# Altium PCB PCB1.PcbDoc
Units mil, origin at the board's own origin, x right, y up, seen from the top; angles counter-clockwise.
Board outline 4950 x 3450 mil, 2 copper layers (Top Layer, Bottom Layer), stack 62 mil thick; 23 components, 0 nets, 12 pads, 0 vias.
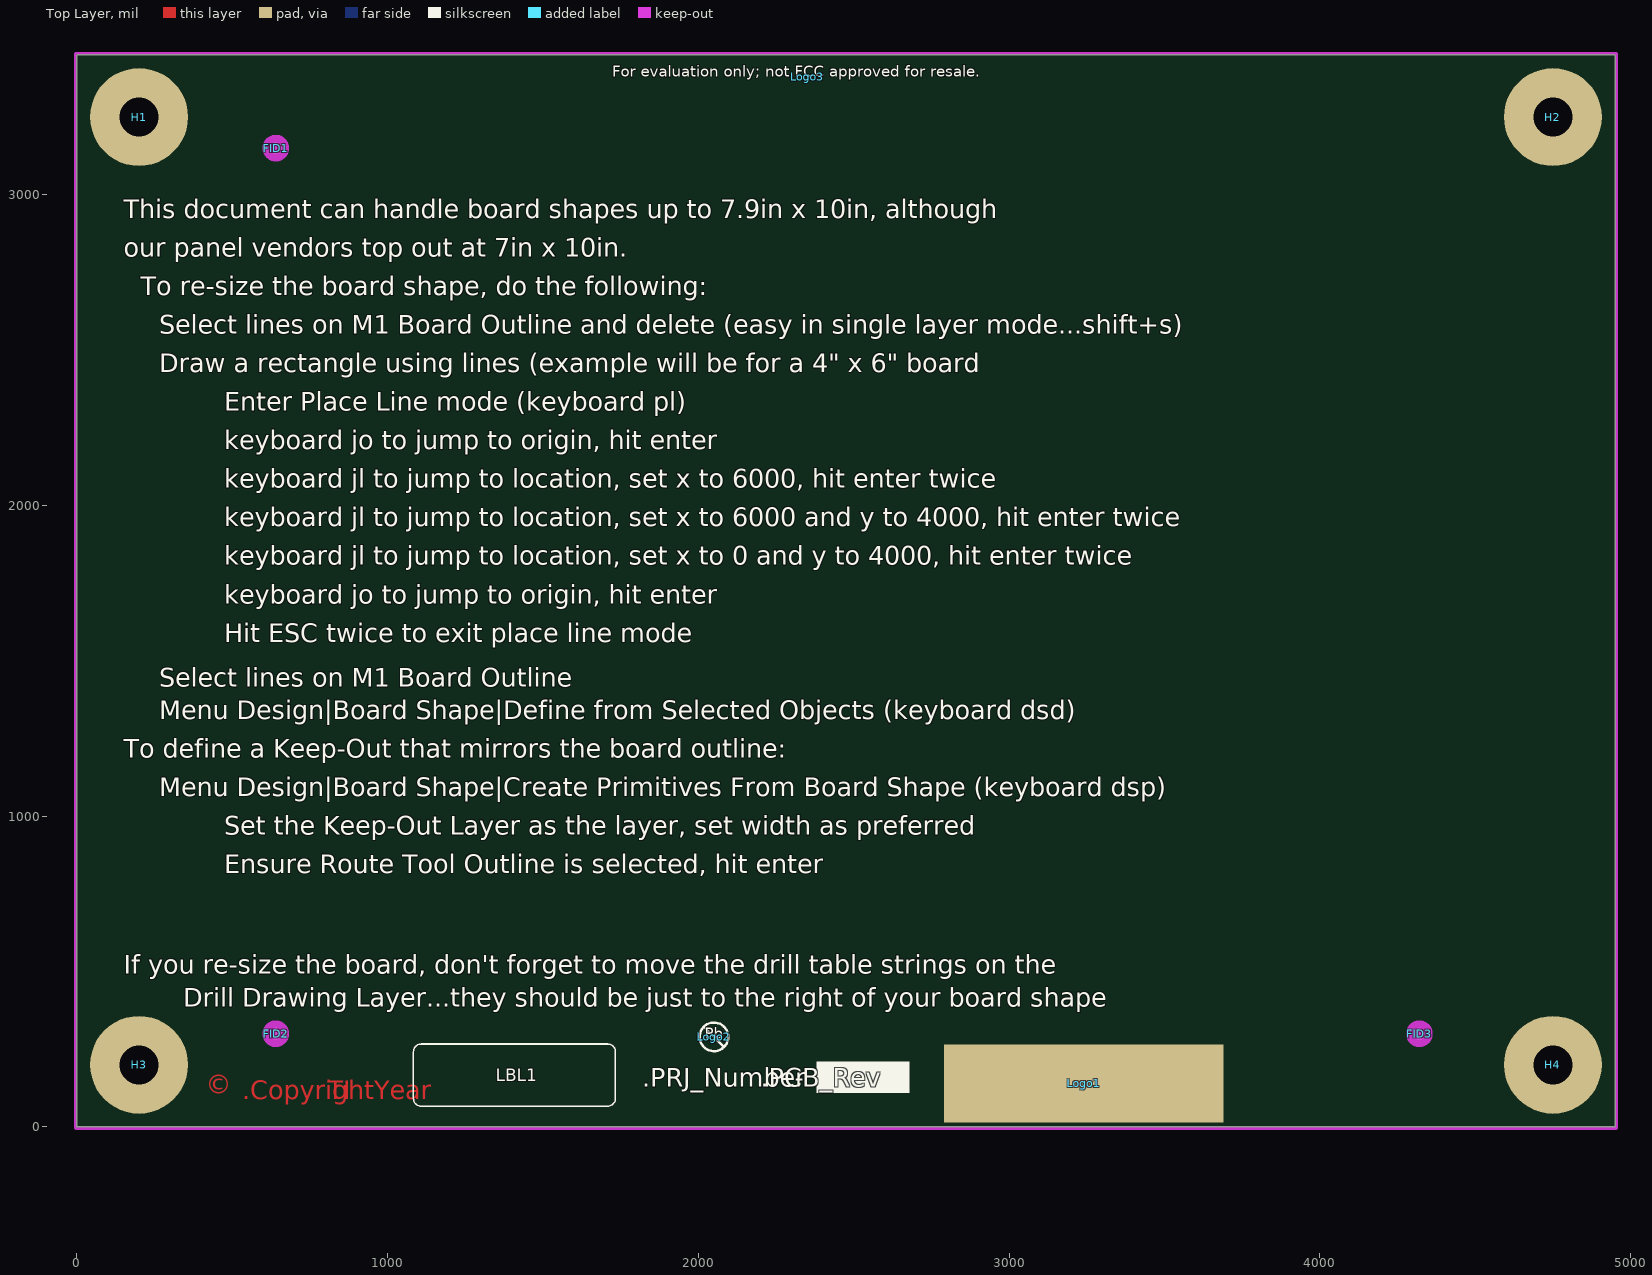
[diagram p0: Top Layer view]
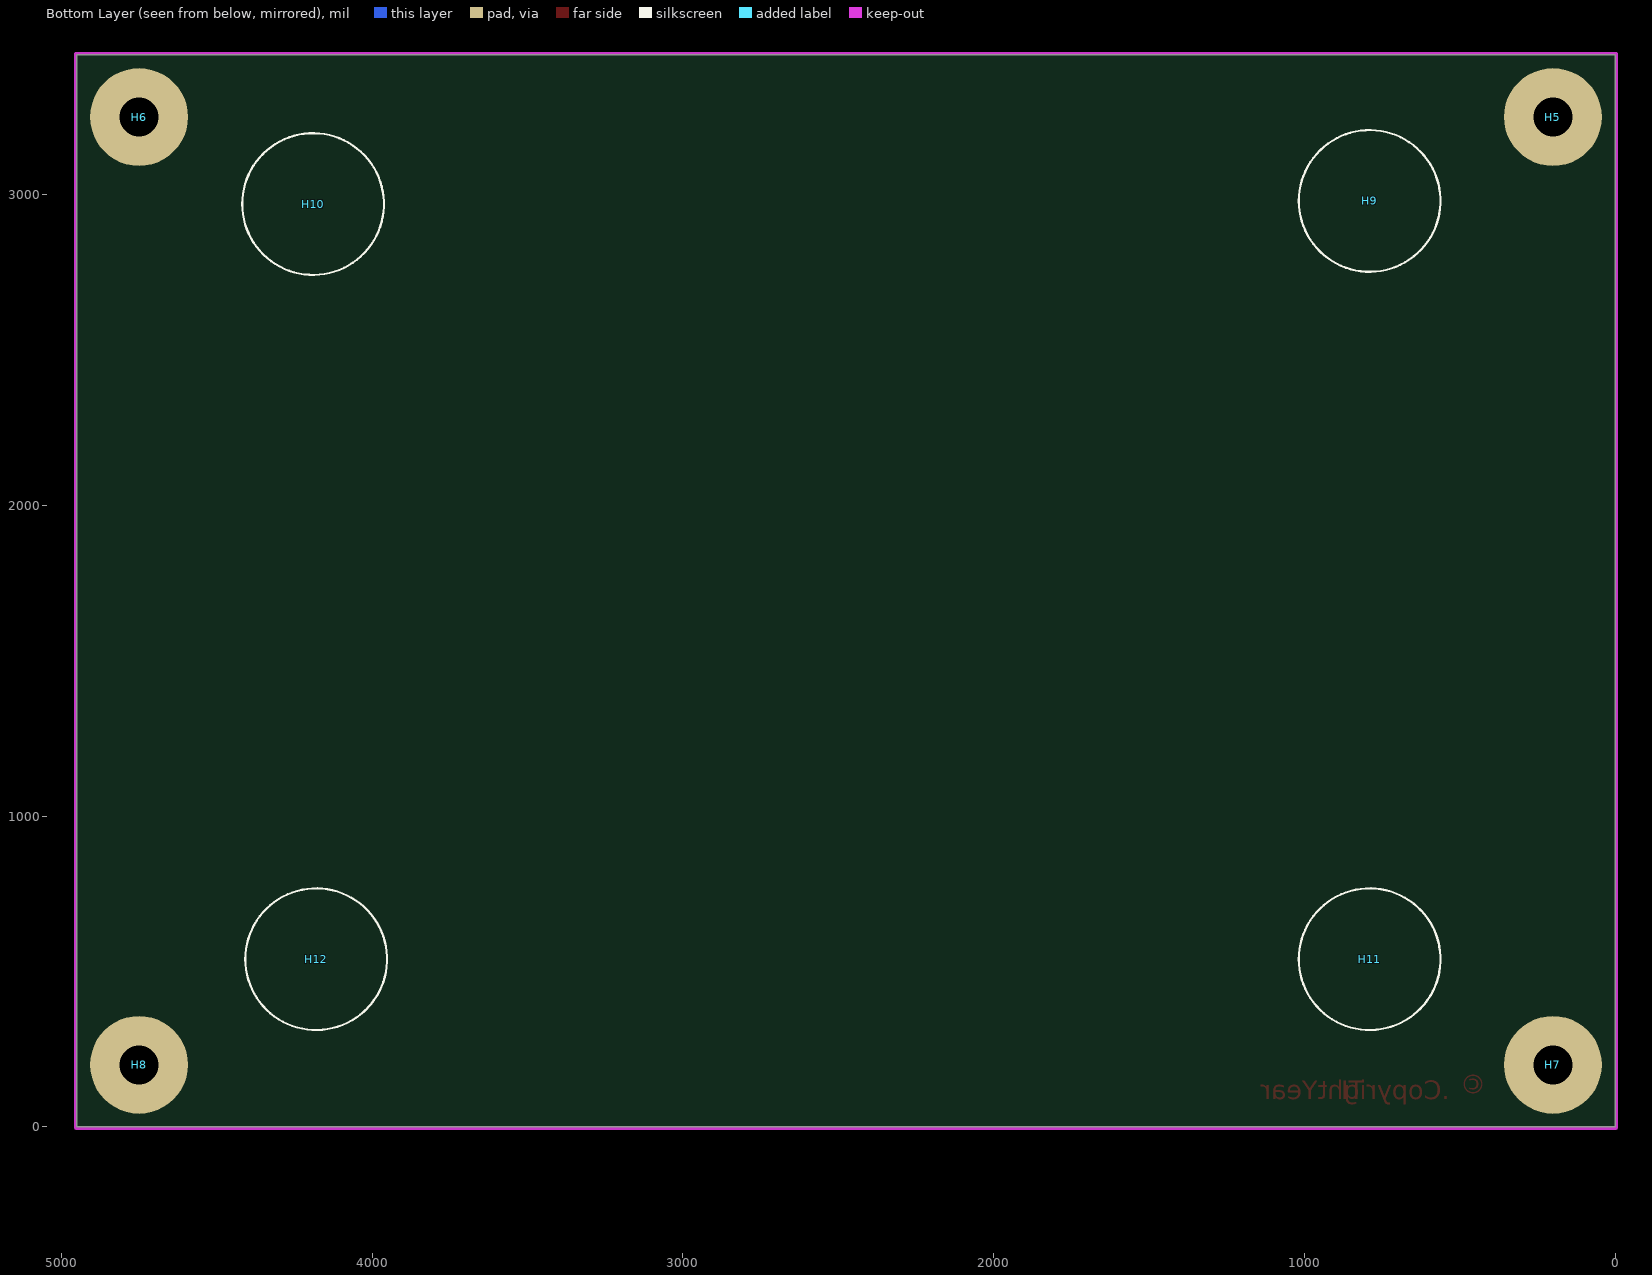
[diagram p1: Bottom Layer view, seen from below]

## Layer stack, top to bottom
Top Solder: solder mask 0.4, Solder Resist, Dk 3.5
Top Layer: signal copper 1.4
Dielectric1: core 59.2, FR-4, Dk 4.8
Bottom Layer: signal copper 1.4
Bottom Solder: solder mask 0.4, Solder Resist, Dk 3.5

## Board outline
0,0 4950,0 4950,3450 0,3450

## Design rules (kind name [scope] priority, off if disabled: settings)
AcuteAngle [All] p1: minimum=4.50000000000000E+0001 checktracksonly=FALSE
AssemblyTestPointUsage [All] p1: valid=2
Clearance Clearance_Keepouts [((IsTrack Or IsArc) And Not InPoly) And IsFree and IsKeepOut vs ((IsTrack Or IsArc) And Not InPoly) And IsFree and IsKeepOut] p1: gap=0
Clearance Clearance_BoardEdge_MountingHoles [OnCopper and InComponentClass('Mounting Holes') vs IsKeepOut] p2: gap=40
Clearance Clearance_BoardEdge_Poly [OnCopper and InPoly vs IsKeepOut] p3: gap=25
Clearance Clearance_BoardEdge [OnCopper and Not InComponentClass('Logo') and not InComponentClass('FiducialMark') and not InRegion(1000,500,4000,800) and Not IsKeepout vs IsKeepOut] p4: gap=75
Clearance Clearance_Poly [InPolygon] p5: gap=25
Clearance [All] p6: gap=7.87
ComponentClearance ComponentClearance_MountingHoles_FiducialMarks [InComponentClass('Mounting Holes') vs InComponentClass('FiducialMark')] p1: gap=50 collisioncheckmode=3 verticalgap=10 showdistances=FALSE
ComponentClearance ComponentClearance_Shunt [InComponentClass('Header') vs InComponentClass('Shunt')] p2: gap=0 collisioncheckmode=3 verticalgap=0 showdistances=FALSE
ComponentClearance ComponentClearance_Logo [InComponentClass('Logo')] p3: gap=50 collisioncheckmode=3 verticalgap=10 showdistances=FALSE
ComponentClearance ComponentClearance_ScrewToNut [(HasFootprint('NY PMS 440 0025 PH')) vs (HasFootprint('Keystone_1902C'))] p4: gap=5 collisioncheckmode=3 verticalgap=10 showdistances=FALSE
ComponentClearance ComponentClearance_MountingHoles [InComponentClass('Mounting Holes')] p5: gap=250 collisioncheckmode=3 verticalgap=100000 showdistances=FALSE
ComponentClearance ComponentClearance_SmallPassives [HasFootprint('0201*') or HasFootprint('0402*') or HasFootprint('0508') or HasFootprint('0603*') or HasFootprint('0612') or HasFootprint('0805*') or HasFootprint('0815*') or HasFootprint('0830*') or HasFootprint('1206*') or HasFootprint('1210*') or HasFootprint('1808*') or HasFootprint('1812*') or HasFootprint('1825*') or HasFootprint('2010*') or HasFootprint('2220*') or HasFootprint('2225*') or HasFootprint('2512*') or HasFootprint('2728*') or HasFootprint('3518*') vs HasFootprint('0201*') or HasFootprint('0402*') or HasFootprint('0508') or HasFootprint('0603*') or HasFootprint('0612') or HasFootprint('0805*') or HasFootprint('0815*') or HasFootprint('0830*') or HasFootprint('1206*') or HasFootprint('1210*') or HasFootprint('1808*') or HasFootprint('1812*') or HasFootprint('1825*') or HasFootprint('2010*') or HasFootprint('2220*') or HasFootprint('2225*') or HasFootprint('2512*') or HasFootprint('2728*') or HasFootprint('3518*')] p6: gap=20 collisioncheckmode=3 verticalgap=10 showdistances=FALSE
ComponentClearance ComponentClearance_THtoSMT [IsThruComponent vs IsSMTComponent] p7: gap=100 collisioncheckmode=3 verticalgap=30 showdistances=FALSE
ComponentClearance ComponentClearance_THtoTH [IsThruComponent vs IsThruComponent] p8: gap=118.11 collisioncheckmode=3 verticalgap=30 showdistances=FALSE
ComponentClearance [All] p9: gap=40 collisioncheckmode=3 verticalgap=10 showdistances=FALSE
DiffPairsRouting [All] p1: maxlimit=100 minlimit=10 mostfreqgap=10 toplayer_minwidth=15 toplayer_maxwidth=15 toplayer_prefwidth=15 bottomlayer_minwidth=15 bottomlayer_maxwidth=15 bottomlayer_prefwidth=15 maxuncoupledlength=1000
FabricationTestPointUsage TestPointUsage [All] p1: valid=2 allowmultiple=FALSE
FabricationTestpoint Testpoint [All] p1: side=3 testpointundercomponent=TRUE minsize=40 maxsize=100 preferedsize=60 minholesize=0 maxholesize=40 preferedholesize=32 testpointgrid=1 allowsidetop=TRUE allowsidebottom=TRUE usegrid=TRUE gridtolerance=0.01
FanoutControl Fanout_LCC [IsLCC] p1: bgadir=Out bgaviamode=Centered fanoutstyle=Auto fanoutdirection=Alternating viagrid=1 // Fanout_LCC (Default Rule)
FanoutControl Fanout_BGA [IsBGA] p2: bgadir=Out bgaviamode=Centered fanoutstyle=Auto fanoutdirection=Alternating viagrid=1 // Fanout_BGA (Default Rule)
FanoutControl Fanout_Default [All] p4: bgadir=Out bgaviamode=Centered fanoutstyle=Auto fanoutdirection=Alternating viagrid=1 // Fanout_Default (Default Rule)
FanoutControl Fanout_Small [(CompPinCount < 5)] p5: bgadir=Out bgaviamode=Centered fanoutstyle=Auto fanoutdirection=OutThenIn viagrid=1 // Fanout_Small (Default Rule)
HoleSize [All] p1: absolutevalues=TRUE maxlimit=251 minlimit=8 maxpercent=80.000 minpercent=20.000
MinimumAnnularRing MinimumAnnularRing_ThermalPadVias [IsVia and InAnyComponent] p1: minimumring=5.91
MinimumAnnularRing [All] p2: minimumring=9
MinimumSolderMaskSliver MinimumSolderMaskSliver_Logo [InComponentClass('Logo') vs InComponentClass('Logo')] p1: minsoldermaskwidth=0.7
MinimumSolderMaskSliver [All] p2: minsoldermaskwidth=3.94
PlaneConnect [All] p1: planeconnectstyle=Relief reliefexpansion=10 reliefentries=4 reliefconductorwidth=10 reliefairgap=10
PolygonConnect [All] p1: connectstyle=Relief reliefconductorwidth=10 reliefentries=4 polygonreliefangle="90 Angle" airgapwidth=10
RoutingVias ThermalPadVias [IsVia and InAnyComponent] p1: holewidth=7.87 width=19.68 viastyle="Through Hole" minholewidth=7.87 minwidth=19.68 maxholewidth=12.99 maxwidth=23.62
RoutingVias [All] p2: holewidth=16 width=34 viastyle="Through Hole" minholewidth=7.87 minwidth=26 maxholewidth=40 maxwidth=65
SilkToBoardRegionClearance [Not ((IsComment or IsDesignator) And (Hide <> 'False')) and not InRegion(1000,500,4000,800)] p1:
SilkToSilkClearance SilkToSilkClearance_Pb-FreeLogo [(HasFootprint('Pb-Free_Overlay_Medium') OR HasFootprint('Pb-Free_Overlay_Small')) vs (HasFootprint('Pb-Free_Overlay_Medium') OR HasFootprint('Pb-Free_Overlay_Small'))] p1: silktosilkclearance=0
SilkToSilkClearance [All] p2: silktosilkclearance=5
SilkToSolderMaskClearance "Silk to Solder Mask Opening" [All] p1: minsilkscreentomaskgap=1 clearancetoexposedcopper=FALSE
SolderMaskExpansion [All] p1: expansion=1.97
UnpouredPolygon [All] p1: allowunpoured=FALSE
Width [All] p1: maxlimit=100 minlimit=6 preferedwidth=10 checkconnectedcopper=TRUE
14 further rules are at their usual default settings.

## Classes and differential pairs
component class "Mounting Holes": H1 H2 H3 H4
component class Logo: Logo1
component class FiducialMark: FID1 FID2 FID3
component class AssemblyNote: ZZ1 ZZ2 ZZ3 ZZ4
component class Label: LBL1

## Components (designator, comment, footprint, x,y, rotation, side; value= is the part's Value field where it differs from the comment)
FID1 "Fiducial" Fiducial10-20 640,3150 r0 top
FID2 "Fiducial" Fiducial10-20 640,300 r0 top
FID3 "Fiducial" Fiducial10-20 4320,300 r0 top
H1 "NY PMS 440 0025 PH" "NY PMS 440 0025 PH" 200,3250 r0 top locked
H2 "NY PMS 440 0025 PH" "NY PMS 440 0025 PH" 4750,3250 r0 top locked
H3 "NY PMS 440 0025 PH" "NY PMS 440 0025 PH" 200,200 r0 top locked
H4 "NY PMS 440 0025 PH" "NY PMS 440 0025 PH" 4750,200 r0 top locked
H5 "1902C" Keystone_1902C 200,3250 r180 bottom locked
H6 "1902C" Keystone_1902C 4750,3250 r180 bottom locked
H7 "1902C" Keystone_1902C 200,200 r180 bottom locked
H8 "1902C" Keystone_1902C 4750,200 r180 bottom locked
H9 "SJ-5303 (CLEAR)" Bumpon_SJ5003Transparent 790,2980 r180 bottom
H10 "SJ-5303 (CLEAR)" Bumpon_SJ5003Transparent 4190,2970 r180 bottom
H11 "SJ-5303 (CLEAR)" Bumpon_SJ5003Transparent 790,540 r180 bottom
H12 "SJ-5303 (CLEAR)" Bumpon_SJ5003Transparent 4180,540 r180 bottom
LBL1 "Size: 0.65\" x 0.20 \"" Label_650x200 1408,167 r0 top
Logo1 "Texas Instruments" TI_Stacked_SolderMask_Small 3240,140 r0 top
Logo2 "Pb-Free Symbol" Pb-Free_Overlay_Small 2050,290 r0 top
Logo3 "FCC disclaimer" FCC_disclaimer 2350,3380 r0 top
ZZ1 "This Assembly Note is for PCB labels only" AssemblyNoteLabel 185,3938 r0 top
ZZ2 "These assemblies are ESD sensitive, ESD precautions shall be observed." AssemblyNote 185,3829.11 r0 top
ZZ3 "These assemblies must be clean and free from flux and all contaminants. Use of no clean flux is not acceptable." AssemblyNote 185,3740.56 r0 top
ZZ4 "These assemblies must comply with workmanship standards IPC-A-610 Class 2, unless otherwise specified." AssemblyNote 185,3652 r0 top

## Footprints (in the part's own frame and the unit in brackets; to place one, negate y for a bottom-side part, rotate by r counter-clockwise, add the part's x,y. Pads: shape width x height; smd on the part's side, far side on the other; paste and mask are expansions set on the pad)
AssemblyNote [mil] "Assembly Note"
AssemblyNoteLabel [mil] "Assembly Note for PCB Labels"
Bumpon_SJ5003Transparent [mil] "3M Hemispherical Bumpon transparent"
  round 1 on Mech4: 0(0,0)
  silkscreen extent -228,-228 228,228, body extent -217,-218 219,218, height 197
FCC_disclaimer [mil]
Fiducial10-20 [mm]
  round 1 smd mask+0.5: 1(0,0)
  Top Layer keep-out circle w1.178: c0,0 r0.5
Keystone_1902C [mil] "Hex Standoff, 4-40 threaded, nylon"
  body extent -145,-126 146,126, height 501
Label_650x200 [mil] "Thermal Transfer Label"
  silkscreen extent -325,-100 325,100, body extent -326,-101 326,101, height 1
"NY PMS 440 0025 PH" [mm] "4-40 nylon screw and mounting hole"
  round 8 hole 3.2: 1(0,0)
  body extent -3.3,-3.3 3.3,3.3, height 2.69
Pb-Free_Overlay_Small [mil]
  silkscreen extent -46,-46 46,46
TI_Stacked_SolderMask_Small [mil]
  rect 900x250 smd paste-125 mask-125: 0(0,0)

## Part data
FID1 FID2 FID3: "Fiducial mark.  There is nothing to buy or mount."
H1 H2 H3 H4: "Machine Screw, Round, #4-40 x 1/4, Nylon, Philips panhead"
H5 H6 H7 H8: "Standoff, Hex, 0.5\"L #4-40 Nylon"
H9 H10 H11 H12: "Bumpon, Hemisphere, 0.44 X 0.20, Clear"
LBL1: library part THT-14-423-10, "Thermal Transfer Printable Labels, 0.650\" W x 0.200\" H - 10,000 per roll"
Logo1: library part TI_Logo, "Texas Instrument Corporate Signature"
Logo2: library part Pb-Free
Logo3: library part FCC_disclaimer, "FCC_disclaimer"
ZZ1: library part AssemblyNoteLabel
ZZ2 ZZ3 ZZ4: library part AssemblyNote

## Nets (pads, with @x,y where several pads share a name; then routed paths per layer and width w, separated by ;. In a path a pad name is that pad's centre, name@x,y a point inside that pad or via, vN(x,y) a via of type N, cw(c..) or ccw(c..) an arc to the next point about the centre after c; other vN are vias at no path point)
pads on no net: FID1.1 FID2.1 FID3.1 H1.1 H2.1 H3.1 H4.1 H9.0 H10.0 H11.0 H12.0 Logo1.0

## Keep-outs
Keep-Out Layer:
  lines w10: -5,0 ccw(c0,0) 0,-5 ; -5,0 ccw(c0,0) 0,-5 ; -5,0 -5,3450 ; -5,3450 cw(c0,3450) 0,3455 ; -5,3450 cw(c0,3450) 0,3455 ; 0,-5 4950,-5 ; 0,3455 4950,3455 ; 4950,-5 ccw(c4950,0) 4955,0 ; 4950,-5 ccw(c4950,0) 4955,0 ; 4950,3455 cw(c4950,3450) 4955,3450 ; 4950,3455 cw(c4950,3450) 4955,3450 ; 4955,0 4955,3450
  text ".Layer_Name" at 577,-858.49 h60

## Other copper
Top Layer:
  text ".CopyrightYear" at 532,90 h60
  text "TI" at 808,90 h60
  text "©" at 415,86.48 h105
  text ".Layer_Name" at 577,-858.49 h60
Bottom Layer:
  text ".Layer_Name" at 577,-858.49 h60

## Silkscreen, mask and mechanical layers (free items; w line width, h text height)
Top Overlay:
  region: 2680,210 2380,210 2380,110 2680,110
  text "This document can handle board shapes up to 7.9in x 10in, although" at 150,2925 h60
  text "our panel vendors top out at 7in x 10in." at 150,2800.94 h60
  text "To re-size the board shape, do the following:" at 205,2676.88 h60
  text "Select lines on M1 Board Outline and delete (easy in single layer mode...shift+s)" at 265,2552.82 h60
  text "Draw a rectangle using lines (example will be for a 4\" x 6\" board" at 265,2428.76 h60
  text "Enter Place Line mode (keyboard pl)" at 475,2304.71 h60
  text "keyboard jo to jump to origin, hit enter" at 475,2180.65 h60
  text "keyboard jl to jump to location, set x to 6000, hit enter twice" at 475,2056.59 h60
  text "keyboard jl to jump to location, set x to 6000 and y to 4000, hit enter twice" at 475,1932.53 h60
  text "keyboard jl to jump to location, set x to 0 and y to 4000, hit enter twice" at 475,1808.47 h60
  text "keyboard jo to jump to origin, hit enter" at 475,1684.41 h60
  text "Hit ESC twice to exit place line mode" at 475,1560.35 h60
  text "Select lines on M1 Board Outline" at 265,1416.3 h60
  text "Menu Design|Board Shape|Define from Selected Objects (keyboard dsd)" at 265,1312.24 h60
  text "To define a Keep-Out that mirrors the board outline:" at 150,1188.18 h60
  text "Menu Design|Board Shape|Create Primitives From Board Shape (keyboard dsp)" at 265,1064.12 h60
  text "Set the Keep-Out Layer as the layer, set width as preferred" at 475,940.06 h60
  text "Ensure Route Tool Outline is selected, hit enter" at 475,816 h60
  text "If you re-size the board, don't forget to move the drill table strings on the" at 150,493 h60
  text "Drill Drawing Layer...they should be just to the right of your board shape" at 343,387 h60
  text ".PRJ_Number" at 1820,130.01 h60
  text ".PCB_Rev" at 2200,130.01 h60
  text "-" at 2310,130.01 h60
  text ".Layer_Name" at 577,-858.49 h60
Bottom Overlay:
  text ".Layer_Name" at 577,-858.49 h60
Top Paste:
  text ".Layer_Name" at 577,-858.49 h60
Bottom Paste:
  text ".Layer_Name" at 577,-858.49 h60
Top Solder:
  text ".Layer_Name" at 577,-858.49 h60
  text ".Layer_Name" at 577,-858.49 h60
Bottom Solder:
  text ".Layer_Name" at 577,-858.49 h60
Drill Guide:
  text ".Layer_Name" at 577,-858.49 h60
M1 Board Outline:
  the board outline again, w10
  text ".Layer_Name" at 577,-858.49 h60
M2 Board Dimensions:
  rectangle: 0,-275 125,-150
  rectangle: 125,-400 500,-275
  lines w7: 0,-275 1000,-275 ; 125,-400 125,-150 ; 250,-400 250,-150 ; 500,-400 500,-150 ; 750,-400 750,-150 ; 0,-400 1000,-400 1000,-150 0,-150 0,-400
  text ".Layer_Name" at 577,-858.49 h60
M3 3D STEP Top:
  text ".Layer_Name" at 577,-858.49 h60
M4 3D STEP Bottom:
  text ".Layer_Name" at 577,-858.49 h60
M5 Assembly Top:
  lines w10: -292,-930.17 6308,-930.17 ; -292,-726.83 6310,-726.83 ; -292,-523.5 -292,-1133.5 3713,-1133.5 6310,-1133.5 6310,-523.5 -291.5,-523.5 -291.5,-1133.5 1284,-1133.5 ; 2173,-1133.5 2173,-523.5 ; 3440,-726.83 3440,-523.5 ; 4280,-726.83 4280,-523.5 ; 4902,-1140 4902,-937.17
  text "COMPONENTS MARKED 'DNP' SHOULD NOT BE POPULATED." at 1153.5,-318.5 h60
  text "ASSEMBLY VARIANT:" at 1153,-434 h60
  text ".VariantName" at 2189,-434 h60
  text "PCB VIEWED FROM TOP SIDE" at -228.5,-655.67 h60
  text "BOARD #:" at 2248,-655.67 h60
  text ".PRJ_Number" at 2793.5,-655.67 h60
  text "REV:" at 3638,-655.67 h60
  text ".PCB_Rev" at 3929.5,-655.67 h60
  text "SVN REV:" at 4476,-655.67 h60
  text ".VersionControl_RevNumber" at 4982,-655.67 h60
  text "TID #:" at 2248,-859 h60
  text ".TID" at 2793.5,-859 h60
  text "PLOT NAME =" at -228.5,-1064.34 h60
  text ".plot_File_Name" at 577,-1064.34 h60
  text "GENERATED    :" at 2250,-1064.34 h60
  text ".Print_Date" at 3119.5,-1064.34 h60
  text ".Print_Time" at 3848.5,-1064.34 h60
  text "TEXAS INSTRUMENTS" at 5113,-1064.34 h60
M6 Assembly Bottom:
  lines w10: -292.5,-727.33 6309.5,-727.33 ; -290.5,-930.67 6309.5,-930.67 ; 1115.5,-1140.5 1115.5,-937.67 ; 1737.5,-727.33 1737.5,-524 ; 2577.5,-727.33 2577.5,-524 ; 3844.5,-1134 3844.5,-524 ; 4733.5,-1134 6309,-1134 6309,-524 -292.5,-524 -292.5,-1134 2304.5,-1134 6309.5,-1134 6309.5,-524
  text "COMPONENTS MARKED 'DNP' SHOULD NOT BE POPULATED." at 6102,-318 h60
  text ".VariantName" at 5058,-434 h60
  text "ASSEMBLY VARIANT:" at 6097,-434 h60
  text ".VersionControl_RevNumber" at 1035.5,-656.17 h60
  text "SVN REV:" at 1541.5,-656.17 h60
  text ".PCB_Rev" at 2088,-656.17 h60
  text "REV:" at 2379.5,-656.17 h60
  text ".PRJ_Number" at 3224,-656.17 h60
  text "BOARD #:" at 3769.5,-656.17 h60
  text "PCB VIEWED FROM BOTTOM SIDE" at 6246,-656.17 h60
  text ".TID" at 3224,-859.5 h60
  text "TID #:" at 3769.5,-859.5 h60
  text "TEXAS INSTRUMENTS" at 904.5,-1064.84 h60
  text ".Print_Time" at 2169,-1064.84 h60
  text ".Print_Date" at 2898,-1064.84 h60
  text "GENERATED    :" at 3767.5,-1064.84 h60
  text ".plot_File_Name" at 5440.5,-1064.84 h60
  text "PLOT NAME =" at 6246,-1064.84 h60
M9 Title Sheet:
  drawing of 57 lines, arcs and shapes, not listed
  text "1" at 739.84,8036.5 h70
  text "2" at 3235.5,8036.5 h70
  text "3" at 5724.84,8036.5 h70
  text "4" at 8231.51,8036.5 h70
  text "5" at 10730.5,8036.5 h70
  text "6" at 13235.5,8036.5 h70
  text "A" at -416.5,6893.5 h70
  text "A" at 14383.5,6893.5 h70
  text "B" at -416.5,4513.5 h70
  text "B" at 14383.5,4513.5 h70
  text "C" at -416.5,2138.5 h70
  text "C" at 14383.5,2138.5 h70
  text "PROJECT TITLE:" at 11343.5,277.5 h45
  text ".PRJ_Title" at 11393.5,144.17 h70
  text "DESIGNED FOR:" at 11343.5,-23.5 h45
  text ".PRJ_Customer" at 11393.5,-163.5 h70
  text "D" at -416.5,-231.5 h70
  text "D" at 14383.5,-231.5 h70
  text "FILE NAME:" at 11343.5,-323.5 h45
  text ".PCB_File_Name_No_Path" at 11393.5,-443.5 h70
  text "Texas Instruments (TI) and/or its licensors do not warrant the accuracy or completeness of this specification" at 6374,-605.34 h45
  text "ENGINEER:" at 11343.5,-613.5 h45
  text "LAYOUT BY:" at 12848.5,-613.5 h45
  text "or any information contained therein. TI and/or its licensors do not warrant that this design will meet" at 6329.01,-718 h45
  text ".PRJ_Engineer" at 11393.5,-768.49 h70
  text ".PCB_Layout" at 12899,-768.49 h70
  text "the specifications, will be suitable for your application or fit for any particular purpose, or will operate in" at 6329.01,-830.67 h45
  text ".Layer_Name" at 577,-858.49 h60
  text "ALTIUM DESIGNER VERSION:" at 12848.5,-923.5 h45
  text "an implementation. TI and/or its licensors do not warrant that the design is production worthy. You should" at 6329.01,-943.33 h45
  text "completely validate and test your design implementation to confirm the system functionality for your application." at 6374,-1056 h45
  text ".print_Scale" at 11393.5,-1056.83 h70
  text ".Application_BuildNumber" at 12899,-1056.83 h70
  text "1" at 739.84,-1263.5 h70
  text "2" at 3235.5,-1263.5 h70
  text "3" at 5724.84,-1263.5 h70
  text "4" at 8231.51,-1263.5 h70
  text "5" at 10730.5,-1263.5 h70
  text "6" at 13235.5,-1263.5 h70
M10 Fab Notes:
  drawing of 185 lines, arcs and shapes, not listed
  text "DESIGN INFORMATION" at 12381.02,5910 h60
  text "MIN. TRACK WIDTH:" at 11736.46,5730 h60
  text "8" at 12832.7,5730 h60
  text "MIL" at 12987.46,5730 h60
  text "MIN. CLEARANCE:" at 11736.46,5598 h60
  text "0.2" at 12772.7,5598 h60
  text "mm" at 12987.46,5598 h60
  text "MIN. VIA PAD SIZE:" at 11736.46,5466 h60
  text "24" at 12802.71,5466 h60
  text "MIL" at 12987.46,5466 h60
  text "0.05mm (2MIL)" at 12431.46,5324.29 h60
  text "MINIMUM ANNULAR RING" at 11407.23,5320 h60
  text "EXTERNAL" at 13139.46,5320 h60
  text "PER" at 11607.23,5202 h60
  text "IPC-D-275 CLASS 2 LEVEL C" at 11827.23,5202 h60
  text "MIL, HOLES" at 13315.46,5089.71 h60
  text "+/-" at 12923,5089 h60
  text "+/-" at 13777,5089 h60
  text "REGISTRATION TOLERANCES:" at 11407.23,5084 h60
  text "METAL" at 12607,5084 h60
  text "5" at 13183.2,5084 h60
  text "3" at 14016.2,5084 h60
  text "MIL" at 14132.46,5084 h60
  text "MATERIAL:" at 11332.46,4874.54 h60
  text "FR-4 High Tg" at 12318.9,4734.21 h60
  text "FR-408" at 11753.46,4725.64 h60
  text "X" at 12165.46,4725.64 h60
  text "OTHER" at 13241.46,4725.64 h60
  text "62 MIL (1.6mm) +/-10%" at 12073.56,4562.92 h60
  text "THICKNESS:" at 11407.23,4558.64 h60
  text "X" at 11945.4,4558.64 h60
  text "OTHER" at 13358.46,4558.64 h60
  text "TOLERANCE:" at 11407.23,4400.64 h60
  text "X" at 12246.53,4400.64 h60
  text "ANSI IPC-6012 TYPE 3 CLASS 2" at 12433.48,4400.64 h60
  text "OTHER +/-" at 12433.46,4244.64 h60
  text "BOW & TWIST:" at 11407.23,4087.64 h60
  text "X" at 12246.53,4087.64 h60
  text "ANSI IPC-6012 TYPE 3 CLASS 2" at 12433.48,4087.64 h60
  text "OTHER +/-" at 12433.46,3929.13 h60
  text "DRILLING:" at 11332.46,3790.64 h60
  text "REFERENCE:" at 11407.23,3673.64 h60
  text "X" at 12055.46,3673.64 h60
  text "AS SHOWN" at 12242.46,3673.64 h60
  text "X" at 12956.46,3673.64 h60
  text "NC_DRILL FILES" at 13093.46,3673.64 h60
  text "PTH MIN COPPER THICKNESS:" at 11407.23,3515.64 h60
  text "X" at 12757.46,3515.64 h60
  text "1MIL" at 12894.46,3515.64 h60
  text "OTHER" at 13391.46,3515.64 h60
  text "BOARD FINISH:" at 11332.46,3356.64 h60
  text "SILKSCREEN:" at 11487.68,3238.64 h60
  text "X" at 12436.46,3238.64 h60
  text "TOP" at 12562.46,3238.64 h60
  text "X" at 12946.46,3238.64 h60
  text "BOTTOM" at 13073.46,3238.64 h60
  text "SILKSCREEN COLOR:" at 11487.68,3071.64 h60
  text "X" at 12435.42,3071.64 h60
  text "WHITE" at 12562.46,3071.64 h60
  text "OTHER" at 13073.46,3071.64 h60
  text "SOLDER RESIST COLOR:" at 11487.68,2901.64 h60
  text "X" at 12055.42,2742.44 h60
  text "GREEN" at 12182.46,2742.44 h60
  text "BLUE" at 12773.46,2742.44 h60
  text "OTHER" at 13311.46,2742.44 h60
  text "IMMERSION GOLD (ENIG)" at 12393.46,2553.92 h60
  text "ENEPIG" at 13731,2550.64 h60
  text "SURFACE FINISH:" at 11332.46,2549.64 h60
  text "X" at 12206.51,2549.64 h60
  text "IMM. TIN/SILVER OR EQUIV" at 11662,2392.64 h60
  text "OTHER" at 13093.46,2392.64 h60
  text "ARRAY/PANEL:" at 11332.46,2213.64 h60
  text "CUT AND TRIM PER MECH LAYER 1" at 12393.46,2209.35 h60
  text "N.C. ROUTE" at 12393.46,2057.64 h60
  text "X" at 13072.46,2057.64 h60
  text "V. SCORE" at 13259.46,2057.64 h60
  text "CERTIFICATION:" at 11332.46,1920.64 h60
  text "MATERIALS AND WORKMANSHIP FOR ALL PCBS" at 12057.46,1920.64 h60
  text "TO MEET OR EXCEED THE REQUIREMENTS OF:" at 12057.46,1822.64 h60
  text "X" at 11683.96,1686.13 h60
  text "ANSI IPC-A-600F CLASS ->" at 11822.96,1686.13 h60
  text "X" at 13462.02,1686.13 h60
  text "2" at 13580.96,1686.14 h60
  text "1" at 13265.96,1684.64 h60
  text "3" at 13934.96,1684.64 h60
  text "X" at 11686.02,1526.64 h60
  text "UL 94V-0" at 11822.96,1526.64 h60
  text "X" at 12498.02,1526.64 h60
  text "RoHS" at 12634.96,1526.64 h60
  text "OTHER" at 13279.36,1526.64 h60
  text "PER ORDER" at 13676.42,1526.64 h60
  text "ADDITIONAL REQUIREMENTS:" at 11332.46,1385.64 h60
  text "MICROSECTION:" at 11407.23,1270.64 h60
  text "YES" at 12312.96,1270.64 h60
  text "REQUIRED" at 13174.46,1114.49 h60
  text "BARE BOARD ELEC. TEST:" at 11407.23,1111.64 h60
  text "NONE" at 12712.96,1111.64 h60
  text "X" at 13047.46,1111.64 h60
  text "PER ORDER" at 13766.46,1111.64 h60
  text "MANUFACTURER'S UL:" at 11407.23,954.64 h60
  text "RAIL" at 12572.96,950.35 h60
  text "METAL" at 13064.77,950.35 h60
  text "X" at 13440,950 h60
  text "SILK" at 13576.46,950.35 h60
  text ".Layer_Name" at 577,-858.49 h60
M11 Gerber Information:
  lines w10: -292,-930.17 6308,-930.17 ; -292,-726.83 6310,-726.83 ; -292,-523.5 -292,-1133.5 3713,-1133.5 6310,-1133.5 6310,-523.5 -291.5,-523.5 -291.5,-1133.5 1284,-1133.5 ; 2173,-1133.5 2173,-523.5 ; 3440,-726.83 3440,-523.5 ; 4280,-726.83 4280,-523.5 ; 4902,-1140 4902,-937.17
  text "ALL ARTWORK VIEWED FROM TOP SIDE" at -228.5,-655.67 h60
  text "BOARD #:" at 2248,-655.67 h60
  text ".PRJ_Number" at 2793.5,-655.67 h60
  text "REV:" at 3638,-655.67 h60
  text ".PCB_Rev" at 3929.5,-655.67 h60
  text "SVN REV:" at 4476,-655.67 h60
  text ".VersionControl_RevNumber" at 4982,-655.67 h60
  text "LAYER NAME =" at -228.5,-858.49 h60
  text "TID #:" at 2248,-859 h60
  text ".TID" at 2793.5,-859 h60
  text "PLOT NAME =" at -228.5,-1064.34 h60
  text ".plot_File_Name" at 577,-1064.34 h60
  text "GENERATED    :" at 2250,-1064.34 h60
  text ".Print_Date" at 3119.5,-1064.34 h60
  text ".Print_Time" at 3848.5,-1064.34 h60
  text "TEXAS INSTRUMENTS" at 5113,-1064.34 h60
M12 Stackup:
  drawing of 191 lines, arcs and shapes, not listed
  text "Layer" at 9790.34,7830 h60
  text "Name" at 10200.26,7830 h60
  text "Material" at 11130,7830 h60
  text "Thickness" at 11989.77,7830 h60
  text "Constant" at 12639.6,7830 h60
  text "Board Layer Stack" at 13209.46,7830 h60
  text "1" at 9790.34,7710 h60
  text "Top Overlay" at 10200.26,7710 h60
  text "2" at 9790.34,7590 h60
  text "Top Solder" at 10200.26,7590 h60
  text "Solder Resist" at 11130,7590 h60
  text "0.40mil" at 11989.77,7590 h60
  text "3.5" at 12639.6,7590 h60
  text "3" at 9790.34,7470 h60
  text "Top Layer" at 10200.26,7470 h60
  text "Copper" at 11130,7470 h60
  text "1.40mil" at 11989.77,7470 h60
  text "4" at 9790.34,7350 h60
  text "Dielectric1" at 10200.26,7350 h60
  text "FR-4" at 11130,7350 h60
  text "59.20mil" at 11989.77,7350 h60
  text "4.8" at 12639.6,7350 h60
  text "5" at 9790.34,7230 h60
  text "Bottom Layer" at 10200.26,7230 h60
  text "Copper" at 11130,7230 h60
  text "1.40mil" at 11989.77,7230 h60
  text "6" at 9790.34,7110 h60
  text "Bottom Solder" at 10200.26,7110 h60
  text "Solder Resist" at 11130,7110 h60
  text "0.40mil" at 11989.77,7110 h60
  text "3.5" at 12639.6,7110 h60
  text "7" at 9790.34,6990 h60
  text "Bottom Overlay" at 10200.26,6990 h60
  text ".Layer_Name" at 577,-858.49 h60
M13 Component Bodies Top:
  text ".Layer_Name" at 577,-858.49 h60
M14 Component Bodies Bottom:
  text ".Layer_Name" at 577,-858.49 h60
M15 Courtyards Top:
  text ".Layer_Name" at 577,-858.49 h60
M16 Courtyards Bottom:
  text ".Layer_Name" at 577,-858.49 h60
Drill Drawing:
  lines w1: 5667.91,3195.85 5717.74,3195.85 5717.74,3245.68 5667.91,3245.68 5667.91,3195.85
  lines w12: 5600,3151 7718.44,3151 ; 5600,3300.5 7718.44,3300.5 ; 5970.51,3001.5 5970.51,3450 ; 6327.67,3001.5 6327.67,3450 ; 6989.15,3001.5 6989.15,3450 ; 7273.35,3001.5 7273.35,3450 ; 5600,3001.5 7718.44,3001.5 7718.44,3450 5600,3450 5600,3001.5
  text "Symbol" at 5689.7,3345.35 h72
  text "Quantity" at 6015.36,3345.35 h72
  text "Finished Hole Size" at 6372.52,3345.35 h72
  text "Plated" at 7034,3345.35 h72
  text "Hole Type" at 7318.2,3345.35 h72
  text "4" at 6015.36,3195.85 h60
  text "125.98mil (3.200mm)" at 6372.52,3195.85 h60
  text "PTH" at 7034,3195.85 h60
  text "Round" at 7318.2,3195.85 h60
  text "4 Total" at 6015.36,3046.35 h60
  text ".Layer_Name" at 577,-858.49 h60

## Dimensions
0,-400 to 1000,-400 on M2 Board Dimensions
0,0 to 0,3450 on M2 Board Dimensions
0,0 to 4950,0 on M2 Board Dimensions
